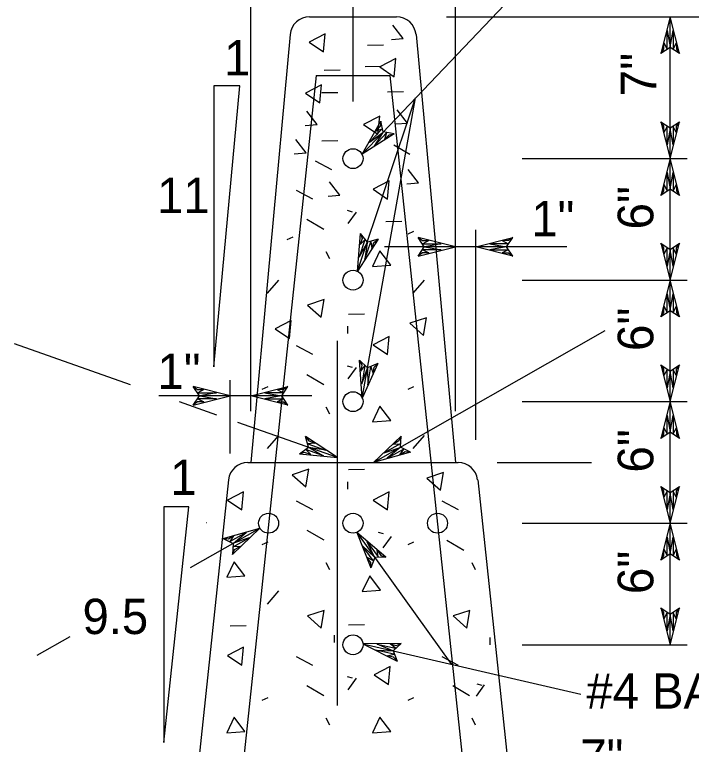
# Model space of a CAD drawing. Extents: x 504255 to 505955, y 659986 to 661086.
# Drawn here: x 504466.9 to 504576.9, y 660217 to 660335.6 of the extents above; entities that cross this region are included whole.
import ezdxf

# ---------------------------------------------------------------- set-up
doc = ezdxf.new("R2010")
doc.units = 0
for name, color, linetype in [('Level1', 7, 'Continuous'), ('Level3', 7, 'Continuous'), ('Level63', 7, 'Continuous')]:
    doc.layers.add(name, color=color, linetype=linetype)

msp = doc.modelspace()

# ---------------------------------------------------------------- linework, layer by layer
at = {"layer": 'Level1'}
for p, q in [((504538.57, 660271.15), (504538.57, 660384.89)), ((504521.94, 660321.46), (504521.94, 660361.89)), ((504523.41, 660312.86), (504561, 660352.36)), ((504505.32, 660271.15), (504505.32, 660344.19)), ((504537.11, 660335.21), (504688.45, 660335.21)), ((504573.48, 660312.16), (504573.48, 660335.21)), ((504511.7, 660332.33), (504505.32, 660262.79)), ((504532.18, 660332.33), (504538.57, 660262.79)), ((504499.34, 660278.34), (504503.53, 660324)), ((504499.34, 660324), (504499.34, 660278.34)), ((504503.53, 660324), (504499.34, 660324)), ((504522.69, 660293.85), (504532.12, 660322.02)), ((504523.45, 660273.26), (504532.12, 660322.02)), ((504549.43, 660312.16), (504576.27, 660312.16)), ((504573.48, 660292.42), (504573.48, 660312.16)), ((504541.88, 660266.48), (504541.88, 660300.59)), ((504538.57, 660297.83), (504527.05, 660297.83)), ((504556.71, 660297.83), (504538.57, 660297.83)), ((504549.43, 660292.42), (504576.27, 660292.42)), ((504573.48, 660272.67), (504573.48, 660292.42)), ((504525.29, 660262.79), (504562.9, 660284.22)), ((504485.8, 660275.43), (504466.94, 660282.06)), ((504519.42, 660223.29), (504519.42, 660282.54)), ((504502, 660264.26), (504502, 660276.15)), ((504502, 660273.62), (504490.38, 660273.62)), ((504515.27, 660273.62), (504502, 660273.62)), ((504499.8, 660270.5), (504493.74, 660272.63)), ((504549.43, 660272.67), (504576.27, 660272.67)), ((504573.48, 660252.92), (504573.48, 660272.67)), ((504519.42, 660263.59), (504503.2, 660269.3)), ((504545.35, 660262.79), (504560.71, 660262.79)), ((504491.19, 660217.29), (504495.26, 660255.59)), ((504495.26, 660255.59), (504491.19, 660255.59)), ((504491.19, 660255.59), (504491.19, 660217.29)), ((504549.43, 660252.92), (504576.27, 660252.92)), ((504573.48, 660233.17), (504573.48, 660252.92)), ((504495.53, 660245.7), (504506.81, 660252.11)), ((504522.54, 660251.42), (504537.94, 660229.99)), ((504470.61, 660231.5), (504475.95, 660234.54)), ((504523.56, 660233.3), (504558.96, 660225.15)), ((504549.43, 660233.17), (504576.27, 660233.17))]:
    msp.add_line(p, q, dxfattribs=at)
for points in [[(504514.88, 660335.21), (504529, 660335.21)], [(504574.99, 660329.23), (504573.48, 660335.21), (504571.97, 660329.23), (504572.48, 660329.94), (504572.48, 660330.97), (504572.98, 660329.97), (504572.98, 660332.96), (504573.48, 660330.3), (504573.98, 660332.96), (504573.98, 660329.97), (504574.49, 660330.97), (504574.49, 660329.94), (504574.99, 660329.23), (504573.48, 660330.22), (504571.97, 660329.23)], [(504515.94, 660325.64), (504499.16, 660167.49)], [(504515.94, 660325.64), (504527.95, 660325.64)], [(504527.95, 660325.64), (504544.77, 660167.15)], [(504528.65, 660316.19), (504523.41, 660312.86), (504526.45, 660318.24), (504526.33, 660317.38), (504525.62, 660316.63), (504526.67, 660317.01), (504524.6, 660314.84), (504526.81, 660316.43), (504525.33, 660314.15), (504527.4, 660316.34), (504527.08, 660315.26), (504527.79, 660316.02), (504528.65, 660316.19), (504526.86, 660316.49), (504526.45, 660318.24)], [(504571.97, 660318.15), (504573.48, 660312.16), (504574.99, 660318.15), (504574.48, 660317.44), (504574.48, 660316.41), (504573.98, 660317.4), (504573.98, 660314.41), (504573.48, 660317.07), (504572.97, 660314.41), (504572.97, 660317.4), (504572.47, 660316.41), (504572.47, 660317.44), (504571.97, 660318.15), (504573.48, 660317.15), (504574.99, 660318.15)], [(504574.99, 660306.19), (504573.48, 660312.16), (504571.97, 660306.19), (504572.48, 660306.9), (504572.48, 660307.93), (504572.98, 660306.93), (504572.98, 660309.92), (504573.48, 660307.26), (504573.98, 660309.92), (504573.98, 660306.93), (504574.49, 660307.93), (504574.49, 660306.9), (504574.99, 660306.19), (504573.48, 660307.19), (504571.97, 660306.19)], [(504526.03, 660299.05), (504522.69, 660293.85), (504523.16, 660299.99), (504523.41, 660299.16), (504523.09, 660298.18), (504523.88, 660298.97), (504522.94, 660296.13), (504524.25, 660298.5), (504523.88, 660295.82), (504524.83, 660298.66), (504525, 660297.55), (504525.32, 660298.53), (504526.03, 660299.05), (504524.27, 660298.57), (504523.16, 660299.99)], [(504532.52, 660296.33), (504538.57, 660297.83), (504532.52, 660299.33), (504533.24, 660298.83), (504534.27, 660298.83), (504533.27, 660298.33), (504536.29, 660298.33), (504533.61, 660297.83), (504536.29, 660297.33), (504533.27, 660297.33), (504534.27, 660296.84), (504533.24, 660296.84), (504532.52, 660296.33), (504533.53, 660297.83), (504532.52, 660299.33)], [(504547.92, 660296.33), (504541.88, 660297.83), (504547.92, 660299.33), (504547.21, 660298.83), (504546.17, 660298.83), (504547.18, 660298.33), (504544.16, 660298.33), (504546.84, 660297.83), (504544.16, 660297.33), (504547.18, 660297.33), (504546.17, 660296.84), (504547.21, 660296.84), (504547.92, 660296.33), (504546.91, 660297.83), (504547.92, 660299.33)], [(504571.97, 660298.4), (504573.48, 660292.42), (504574.99, 660298.4), (504574.48, 660297.69), (504574.48, 660296.66), (504573.98, 660297.65), (504573.98, 660294.67), (504573.48, 660297.32), (504572.97, 660294.67), (504572.97, 660297.65), (504572.47, 660296.66), (504572.47, 660297.69), (504571.97, 660298.4), (504573.48, 660297.4), (504574.99, 660298.4)], [(504574.99, 660286.44), (504573.48, 660292.42), (504571.97, 660286.44), (504572.48, 660287.15), (504572.48, 660288.18), (504572.98, 660287.18), (504572.98, 660290.17), (504573.48, 660287.51), (504573.98, 660290.17), (504573.98, 660287.18), (504574.49, 660288.18), (504574.49, 660287.15), (504574.99, 660286.44), (504573.48, 660287.43), (504571.97, 660286.44)], [(504525.99, 660278.89), (504523.45, 660273.26), (504523.01, 660279.4), (504523.38, 660278.62), (504523.21, 660277.61), (504523.88, 660278.5), (504523.36, 660275.55), (504524.31, 660278.09), (504524.34, 660275.38), (504524.86, 660278.33), (504525.19, 660277.26), (504525.37, 660278.28), (504525.99, 660278.89), (504524.32, 660278.16), (504523.01, 660279.4)], [(504571.97, 660278.65), (504573.48, 660272.67), (504574.99, 660278.65), (504574.48, 660277.94), (504574.48, 660276.91), (504573.98, 660277.91), (504573.98, 660274.91), (504573.48, 660277.57), (504572.97, 660274.91), (504572.97, 660277.91), (504572.47, 660276.91), (504572.47, 660277.94), (504571.97, 660278.65), (504573.48, 660277.65), (504574.99, 660278.65)], [(504495.96, 660272.12), (504502, 660273.62), (504495.96, 660275.12), (504496.67, 660274.62), (504497.71, 660274.62), (504496.7, 660274.12), (504499.73, 660274.12), (504497.05, 660273.62), (504499.73, 660273.12), (504496.7, 660273.12), (504497.71, 660272.62), (504496.67, 660272.62), (504495.96, 660272.12), (504496.97, 660273.62), (504495.96, 660275.12)], [(504511.36, 660272.12), (504505.32, 660273.62), (504511.36, 660275.12), (504510.65, 660274.62), (504509.61, 660274.62), (504510.61, 660274.12), (504507.59, 660274.12), (504510.27, 660273.62), (504507.59, 660273.12), (504510.61, 660273.12), (504509.61, 660272.62), (504510.65, 660272.62), (504511.36, 660272.12), (504510.35, 660273.62), (504511.36, 660275.12)], [(504574.99, 660266.69), (504573.48, 660272.67), (504571.97, 660266.69), (504572.48, 660267.4), (504572.48, 660268.43), (504572.98, 660267.43), (504572.98, 660270.42), (504573.48, 660267.76), (504573.98, 660270.42), (504573.98, 660267.43), (504574.49, 660268.43), (504574.49, 660267.4), (504574.99, 660266.69), (504573.48, 660267.69), (504571.97, 660266.69)], [(504513.23, 660264.19), (504519.42, 660263.59), (504514.24, 660267), (504514.75, 660266.29), (504515.73, 660265.95), (504514.61, 660265.82), (504517.46, 660264.81), (504514.76, 660265.23), (504517.12, 660263.87), (504514.27, 660264.88), (504515.06, 660264.07), (504514.07, 660264.42), (504513.23, 660264.19), (504514.68, 660265.26), (504514.24, 660267)], [(504531.27, 660264.48), (504525.29, 660262.79), (504529.77, 660267.06), (504529.4, 660266.28), (504528.5, 660265.76), (504529.63, 660265.83), (504527, 660264.34), (504529.58, 660265.23), (504527.5, 660263.48), (504530.12, 660264.97), (504529.5, 660264.04), (504530.4, 660264.55), (504531.27, 660264.48), (504529.65, 660265.27), (504529.77, 660267.06)], [(504504.86, 660262.79), (504539.02, 660262.79)], [(504501.68, 660259.96), (504495.34, 660200.24)], [(504542.2, 660259.96), (504548.54, 660200.24)], [(504571.97, 660258.9), (504573.48, 660252.92), (504574.99, 660258.9), (504574.48, 660258.19), (504574.48, 660257.16), (504573.98, 660258.15), (504573.98, 660255.17), (504573.48, 660257.82), (504572.97, 660255.17), (504572.97, 660258.15), (504572.47, 660257.16), (504572.47, 660258.19), (504571.97, 660258.9), (504573.48, 660257.9), (504574.99, 660258.9)], [(504574.99, 660246.94), (504573.48, 660252.92), (504571.97, 660246.94), (504572.48, 660247.65), (504572.48, 660248.68), (504572.98, 660247.68), (504572.98, 660250.67), (504573.48, 660248.01), (504573.98, 660250.67), (504573.98, 660247.68), (504574.49, 660248.68), (504574.49, 660247.65), (504574.99, 660246.94), (504573.48, 660247.94), (504571.97, 660246.94)], [(504500.82, 660250.43), (504506.81, 660252.11), (504502.33, 660247.84), (504502.69, 660248.63), (504503.6, 660249.14), (504502.47, 660249.08), (504505.09, 660250.57), (504502.51, 660249.68), (504504.59, 660251.43), (504501.97, 660249.94), (504502.59, 660250.87), (504501.69, 660250.35), (504500.82, 660250.43), (504502.44, 660249.64), (504502.33, 660247.84)], [(504527.27, 660247.42), (504522.54, 660251.42), (504524.81, 660245.69), (504524.81, 660246.55), (504524.21, 660247.39), (504525.2, 660246.87), (504523.45, 660249.31), (504525.41, 660247.42), (504524.26, 660249.89), (504526.02, 660247.44), (504525.84, 660248.55), (504526.44, 660247.7), (504527.27, 660247.42), (504525.46, 660247.37), (504524.81, 660245.69)], [(504571.97, 660239.15), (504573.48, 660233.17), (504574.99, 660239.15), (504574.48, 660238.44), (504574.48, 660237.41), (504573.98, 660238.41), (504573.98, 660235.42), (504573.48, 660238.07), (504572.97, 660235.42), (504572.97, 660238.41), (504572.47, 660237.41), (504572.47, 660238.44), (504571.97, 660239.15), (504573.48, 660238.15), (504574.99, 660239.15)], [(504529.79, 660233.4), (504523.56, 660233.3), (504529.1, 660230.5), (504528.52, 660231.14), (504527.51, 660231.38), (504528.6, 660231.63), (504525.66, 660232.31), (504528.39, 660232.19), (504525.88, 660233.28), (504528.83, 660232.6), (504527.96, 660233.31), (504528.97, 660233.07), (504529.79, 660233.4), (504528.46, 660232.18), (504529.1, 660230.5)]]:
    msp.add_lwpolyline(points, dxfattribs=at)
for centre, start_param, end_param in [((504514.88, 660332.04), 4.712389, 6.192092), ((504529, 660332.04), 3.232686, 4.712389), ((504504.86, 660259.63), 4.712389, 6.178514), ((504539.02, 660259.63), 3.24706, 4.712389)]:
    msp.add_ellipse(centre, major_axis=(-3.19, 0), ratio=0.99, start_param=start_param, end_param=end_param, dxfattribs=at)
at = {"layer": 'Level3'}
for p, q in [((504526.9, 660330.57), (504524.29, 660330.52)), ((504526.54, 660327.13), (504523.93, 660327.09)), ((504519.85, 660326.55), (504517.24, 660326.5)), ((504519.49, 660322.87), (504516.88, 660322.83)), ((504530.13, 660322.99), (504527.52, 660322.94)), ((504519.49, 660315.06), (504516.88, 660315.02)), ((504528.56, 660314.41), (504531.18, 660312.88)), ((504515.8, 660311.78), (504518.45, 660310.37)), ((504512.68, 660307.04), (504515.34, 660305.63)), ((504521.84, 660303.47), (504521.05, 660303.71)), ((504522.43, 660303.47), (504521.1, 660301.62)), ((504514.44, 660302.32), (504517.18, 660300.72)), ((504529.89, 660301.93), (504527.27, 660301.88)), ((504530.89, 660299.95), (504531.83, 660300.39)), ((504511.25, 660299), (504512.19, 660299.44)), ((504517.54, 660297.07), (504518.1, 660295.92)), ((504509.81, 660292.43), (504507.97, 660290.3)), ((504533.5, 660292.43), (504531.67, 660290.3)), ((504523.8, 660286.89), (504521.18, 660286.85)), ((504521.05, 660284.92), (504521.05, 660283.73)), ((504512.68, 660281.79), (504515.34, 660280.38)), ((504521.84, 660278.23), (504521.05, 660278.45)), ((504514.44, 660277.07), (504517.18, 660275.46)), ((504522.43, 660278.23), (504521.1, 660276.37)), ((504507.2, 660274.7), (504508.13, 660275.13)), ((504530.89, 660274.7), (504531.83, 660275.13)), ((504517.54, 660271.82), (504518.1, 660270.67)), ((504509.81, 660267.17), (504507.97, 660265.05)), ((504533.5, 660267.17), (504531.67, 660265.05)), ((504523.8, 660261.65), (504521.18, 660261.6)), ((504521.05, 660259.66), (504521.05, 660258.47)), ((504512.68, 660256.54), (504515.34, 660255.13)), ((504536.38, 660256.54), (504539.04, 660255.13)), ((504498.14, 660252.97), (504498.05, 660253)), ((504514.44, 660251.81), (504517.18, 660250.21)), ((504526.87, 660251.18), (504526.09, 660251.41)), ((504507.2, 660249.44), (504508.13, 660249.88)), ((504528.14, 660250.75), (504526.81, 660248.9)), ((504530.89, 660249.44), (504531.83, 660249.88)), ((504537.21, 660250.14), (504539.95, 660248.54)), ((504517.54, 660246.56), (504518.1, 660245.42)), ((504541.24, 660246.56), (504541.8, 660245.42)), ((504509.81, 660241.92), (504507.97, 660239.79)), ((504504.59, 660236.24), (504501.97, 660236.18)), ((504523.8, 660236.39), (504521.18, 660236.34)), ((504518.88, 660234.72), (504518.88, 660233.53)), ((504544.16, 660234.35), (504544.16, 660233.16)), ((504512.68, 660231.29), (504515.34, 660229.88)), ((504536.38, 660231.29), (504539.04, 660229.88)), ((504521.84, 660227.72), (504521.05, 660227.95)), ((504522.43, 660227.72), (504521.1, 660225.87)), ((504514.44, 660226.56), (504517.18, 660224.95)), ((504538.14, 660226.56), (504540.88, 660224.95)), ((504543.26, 660226.66), (504541.94, 660224.8)), ((504542.91, 660226.54), (504542.12, 660226.76)), ((504507.2, 660224.19), (504508.13, 660224.62)), ((504530.89, 660224.19), (504531.83, 660224.62)), ((504517.54, 660221.31), (504518.1, 660220.17)), ((504541.24, 660221.31), (504541.8, 660220.17))]:
    msp.add_line(p, q, dxfattribs=at)
for points in [[(504528.17, 660331.53), (504530.07, 660331.67), (504528.41, 660333.83)], [(504514.19, 660317.56), (504516.09, 660317.7), (504514.44, 660319.86)], [(504528.89, 660317.8), (504530.79, 660317.94), (504529.13, 660320.1)], [(504512.4, 660312.95), (504514.3, 660313.09), (504512.65, 660315.25)], [(504530.68, 660308.09), (504532.58, 660308.23), (504530.93, 660310.4)], [(504517.9, 660306.08), (504519.8, 660306.22), (504518.14, 660308.39)]]:
    msp.add_lwpolyline(points, dxfattribs=at)
for points in [[(504514.83, 660331.09), (504517.16, 660329.5), (504517.44, 660332.44)], [(504526.3, 660327.07), (504528.63, 660325.47), (504528.91, 660328.41)], [(504514.23, 660322.8), (504516.56, 660321.21), (504516.84, 660324.15)], [(504523.67, 660317.72), (504526, 660316.12), (504526.28, 660319.06)], [(504525.23, 660307.18), (504527.55, 660305.59), (504527.84, 660308.53)], [(504526.3, 660297.18), (504525.11, 660294.64), (504528.09, 660294.85)], [(504517.23, 660289.26), (504514.55, 660288.37), (504516.76, 660286.38)], [(504509.29, 660284.53), (504511.62, 660282.94), (504511.91, 660285.88)], [(504533.87, 660286.3), (504531.19, 660285.41), (504533.39, 660283.42)], [(504525.23, 660281.93), (504527.55, 660280.34), (504527.84, 660283.28)], [(504526.3, 660271.93), (504525.11, 660269.38), (504528.09, 660269.6)], [(504514.75, 660261.69), (504512.07, 660260.79), (504514.28, 660258.81)], [(504536.62, 660261.17), (504533.94, 660260.26), (504536.15, 660258.28)], [(504501.52, 660256.68), (504503.85, 660255.08), (504504.14, 660258.02)], [(504525.23, 660256.68), (504527.55, 660255.08), (504527.84, 660258.02)], [(504502.6, 660246.67), (504501.41, 660244.13), (504504.38, 660244.36)], [(504524.65, 660244.35), (504523.45, 660241.81), (504526.43, 660242.03)], [(504517.23, 660238.75), (504514.55, 660237.86), (504516.76, 660235.87)], [(504540.93, 660238.75), (504538.24, 660237.86), (504540.46, 660235.87)], [(504501.52, 660231.42), (504503.85, 660229.84), (504504.14, 660232.76)], [(504525.37, 660228.28), (504527.69, 660226.69), (504527.98, 660229.62)], [(504502.6, 660221.42), (504501.41, 660218.88), (504504.38, 660219.1)], [(504526.3, 660221.42), (504525.11, 660218.88), (504528.09, 660219.1)]]:
    msp.add_lwpolyline(points, close=True, dxfattribs=at)
at = {"layer": 'Level63'}
for centre, major_axis in [((504521.94, 660312.16), (1.63, 0)), ((504521.94, 660292.41), (1.63, 0)), ((504521.94, 660272.67), (1.63, 0)), ((504508.22, 660252.92), (1.63, 0)), ((504521.94, 660252.92), (1.63, 0)), ((504535.67, 660252.92), (-1.63, 0)), ((504521.94, 660233.17), (1.63, 0))]:
    msp.add_ellipse(centre, major_axis=major_axis, ratio=0.99, dxfattribs=at)

# ---------------------------------------------------------------- texts
at = {"layer": 'Level1'}
for s, height, p in [('1', 5.74, (504501, 660325.67)), ('11', 5.739, (504490.1, 660303.32)), ('1"', 5.739, (504550.92, 660299.55)), ('1"', 5.739, (504490.17, 660274.75)), ('1', 5.74, (504492.24, 660257.51)), ('9.5', 5.739, (504477.98, 660234.91)), ('#4 BARS CONTINUOUS', 5.7392, (504559.87, 660222.79)), ('7"', 5.739, (504558.89, 660212.05))]:
    msp.add_text(s, height=height, dxfattribs=at).set_placement(p)
for s, p in [('7"', (504571.24, 660322.28)), ('6"', (504570.75, 660300.64)), ('6"', (504570.75, 660280.89)), ('6"', (504570.75, 660261.14)), ('6"', (504570.75, 660241.39))]:
    msp.add_text(s, height=5.797, rotation=90, dxfattribs=at).set_placement(p)

doc.saveas('drawing.dxf')
